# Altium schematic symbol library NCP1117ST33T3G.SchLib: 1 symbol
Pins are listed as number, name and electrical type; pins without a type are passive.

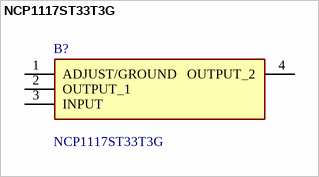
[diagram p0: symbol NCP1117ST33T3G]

## NCP1117ST33T3G
designator B?
ON SEMICONDUCTOR - NCP1117ST33T3G - IC, LINEAR VOLTAGE REGULATOR; Manufacturer_Name: onsemi; Geometry.Height: 1.8mm
footprint SOT230P700X180-4N
pins: 1 ADJUST/GROUND, 2 OUTPUT_1, 3 INPUT, 4 OUTPUT_2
